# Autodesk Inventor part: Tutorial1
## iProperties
Shininess: 64.0
Length Units: 11269
Angle Units: 11279
Time Units: 11290
Mass Units: 11283
Length Display Precision: 3
Angle Display Precision: 2
Compacted: True
Part Number: Tutorial1
Document SubType Name: Modeling
Created: 2002-12
Designer: deepak
Density: 0.0
Volumn: 0.0
Area: 0.0
PropertySet Name: Model Information
Control State: 0
Master: False
Checked Out: False
Author: deepak
